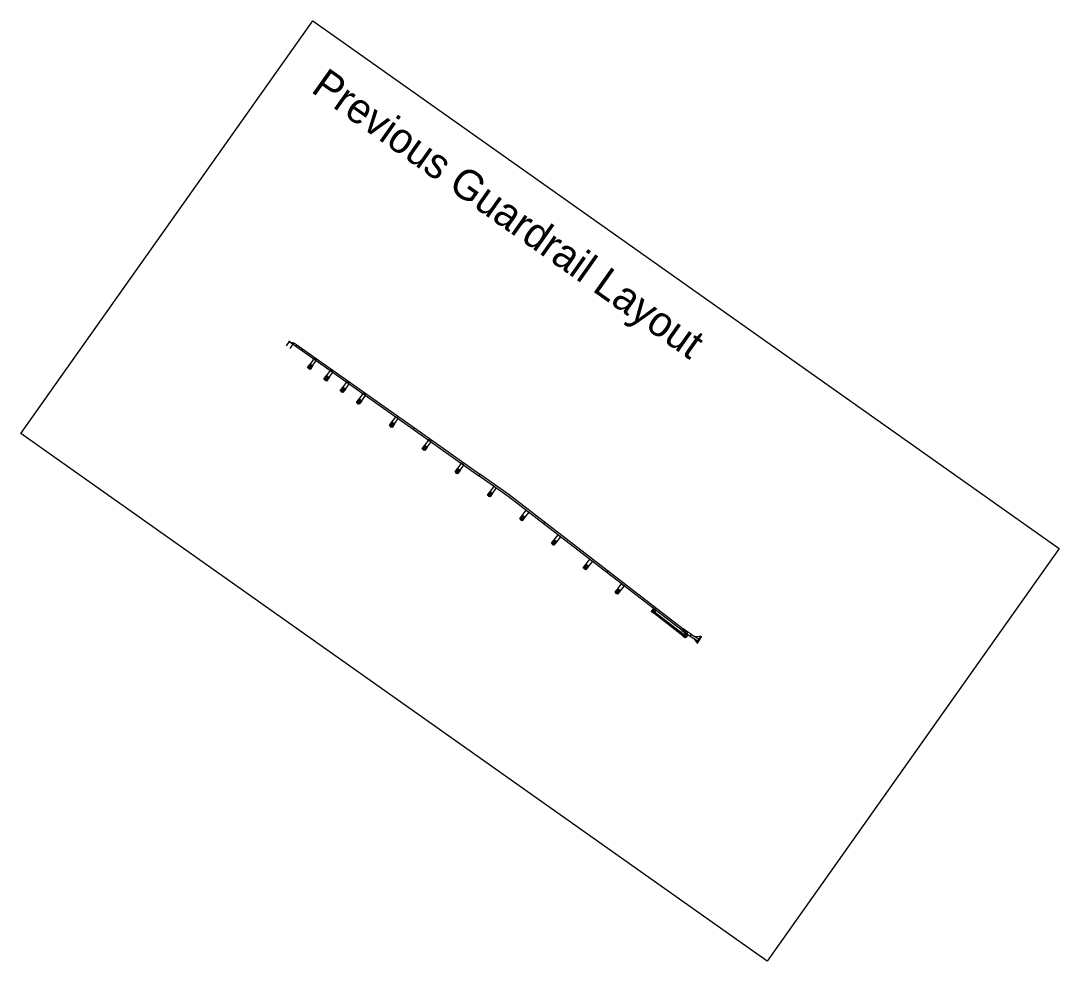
# Model space of a CAD drawing. Extents: x 16457860 to 16462445, y 6896068 to 6900243.
# Drawn here: x 16460800.2 to 16460961.9, y 6896067.7 to 6896214.1 of the extents above; entities that cross this region are included whole.
import ezdxf

# ---------------------------------------------------------------- set-up
doc = ezdxf.new("R2010")
doc.units = 0
doc.layers.add('Barrier', color=7, linetype='Continuous')
doc.layers.add('Draft_DNC', color=7, linetype='Continuous')

msp = doc.modelspace()

# ---------------------------------------------------------------- linework, layer by layer
at = {"layer": 'Barrier'}
for p, q in [((16460841.63, 6896163.5), (16460842.1, 6896164.17)), ((16460841.95, 6896164.24), (16460841.96, 6896164.26)), ((16460841.95, 6896164.24), (16460861.35, 6896150.51)), ((16460842.17, 6896164.12), (16460841.96, 6896164.26)), ((16460842.17, 6896163.11), (16460842.75, 6896163.93)), ((16460842.65, 6896163.96), (16460842.5, 6896164)), ((16460843.16, 6896163.72), (16460843, 6896163.5)), ((16460843.08, 6896163.77), (16460861.51, 6896150.73)), ((16460843.65, 6896163.37), (16460843.5, 6896163.15)), ((16460843.65, 6896163.37), (16460843.5, 6896163.15)), ((16460844.15, 6896163.02), (16460843.99, 6896162.8)), ((16460845.84, 6896161.49), (16460845.27, 6896160.67)), ((16460845.67, 6896160.38), (16460846.25, 6896161.2)), ((16460846.25, 6896161.2), (16460845.84, 6896161.49)), ((16460845.67, 6896160.38), (16460844.88, 6896160.13)), ((16460845.29, 6896159.84), (16460844.88, 6896160.13)), ((16460845.02, 6896160.03), (16460845.01, 6896160.01)), ((16460845.14, 6896159.92), (16460845.01, 6896160.01)), ((16460845.04, 6896159.99), (16460845.02, 6896159.96)), ((16460845.09, 6896159.92), (16460845.02, 6896159.96)), ((16460845.06, 6896159.98), (16460845.03, 6896159.95)), ((16460845.05, 6896159.94), (16460845.03, 6896159.92)), ((16460845.05, 6896159.91), (16460845.03, 6896159.92)), ((16460845.06, 6896159.93), (16460845.05, 6896159.91)), ((16460845.1, 6896159.95), (16460845.07, 6896159.92)), ((16460845.47, 6896160.53), (16460845.09, 6896159.98)), ((16460845.11, 6896159.95), (16460845.09, 6896159.92)), ((16460845.15, 6896159.94), (16460845.14, 6896159.92)), ((16460845.27, 6896160.67), (16460845.67, 6896160.38)), ((16460845.27, 6896160.67), (16460845.29, 6896159.84)), ((16460848.39, 6896159.68), (16460847.82, 6896158.87)), ((16460848.8, 6896159.39), (16460848.39, 6896159.68)), ((16460848.23, 6896158.58), (16460847.43, 6896158.32)), ((16460847.84, 6896158.03), (16460847.43, 6896158.32)), ((16460847.57, 6896158.22), (16460847.56, 6896158.21)), ((16460847.69, 6896158.12), (16460847.56, 6896158.21)), ((16460847.59, 6896158.19), (16460847.57, 6896158.16)), ((16460847.64, 6896158.11), (16460847.57, 6896158.16)), ((16460847.6, 6896158.14), (16460847.58, 6896158.12)), ((16460847.6, 6896158.1), (16460847.58, 6896158.12)), ((16460847.61, 6896158.18), (16460847.59, 6896158.15)), ((16460847.61, 6896158.13), (16460847.6, 6896158.1)), ((16460847.65, 6896158.15), (16460847.62, 6896158.12)), ((16460848.02, 6896158.72), (16460847.64, 6896158.18)), ((16460847.66, 6896158.14), (16460847.64, 6896158.11)), ((16460847.7, 6896158.13), (16460847.69, 6896158.12)), ((16460847.82, 6896158.87), (16460848.23, 6896158.58)), ((16460847.82, 6896158.87), (16460847.84, 6896158.03)), ((16460848.23, 6896158.58), (16460848.8, 6896159.39)), ((16460850.78, 6896156.77), (16460849.98, 6896156.52)), ((16460850.39, 6896156.23), (16460849.98, 6896156.52)), ((16460850.12, 6896156.42), (16460850.11, 6896156.41)), ((16460850.24, 6896156.31), (16460850.11, 6896156.41)), ((16460850.15, 6896156.38), (16460850.12, 6896156.35)), ((16460850.19, 6896156.31), (16460850.12, 6896156.35)), ((16460850.15, 6896156.33), (16460850.13, 6896156.31)), ((16460850.15, 6896156.3), (16460850.13, 6896156.31)), ((16460850.16, 6896156.37), (16460850.14, 6896156.34)), ((16460850.16, 6896156.32), (16460850.15, 6896156.3)), ((16460850.2, 6896156.35), (16460850.18, 6896156.31)), ((16460850.57, 6896156.92), (16460850.19, 6896156.37)), ((16460850.21, 6896156.34), (16460850.19, 6896156.31)), ((16460850.25, 6896156.33), (16460850.24, 6896156.31)), ((16460850.95, 6896157.88), (16460850.37, 6896157.06)), ((16460850.37, 6896157.06), (16460850.78, 6896156.77)), ((16460850.37, 6896157.06), (16460850.39, 6896156.23)), ((16460850.78, 6896156.77), (16460851.35, 6896157.59)), ((16460851.35, 6896157.59), (16460850.95, 6896157.88)), ((16460852.53, 6896154.71), (16460853.33, 6896154.97)), ((16460853.12, 6896155.11), (16460852.74, 6896154.57)), ((16460853.5, 6896156.07), (16460852.92, 6896155.26)), ((16460852.92, 6896155.26), (16460853.33, 6896154.97)), ((16460852.94, 6896154.42), (16460852.92, 6896155.26)), ((16460853.33, 6896154.97), (16460853.91, 6896155.78)), ((16460853.91, 6896155.78), (16460853.5, 6896156.07)), ((16460852.68, 6896154.49), (16460852.68, 6896154.48)), ((16460858.23, 6896151.5), (16460857.84, 6896150.96)), ((16460858.6, 6896152.46), (16460858.02, 6896151.65)), ((16460858.02, 6896151.65), (16460858.43, 6896151.36)), ((16460858.04, 6896150.81), (16460858.02, 6896151.65)), ((16460858.43, 6896151.36), (16460859.01, 6896152.17)), ((16460859.01, 6896152.17), (16460858.6, 6896152.46)), ((16460857.64, 6896151.1), (16460858.43, 6896151.36)), ((16460857.78, 6896150.88), (16460857.78, 6896150.87)), ((16460861.51, 6896150.73), (16460861.35, 6896150.51)), ((16460861.51, 6896150.73), (16460861.35, 6896150.51)), ((16460861.35, 6896150.51), (16460871.56, 6896143.29)), ((16460861.51, 6896150.73), (16460871.72, 6896143.51)), ((16460863.7, 6896148.85), (16460863.12, 6896148.04)), ((16460863.53, 6896147.75), (16460864.11, 6896148.56)), ((16460864.11, 6896148.56), (16460863.7, 6896148.85)), ((16460862.74, 6896147.49), (16460863.53, 6896147.75)), ((16460862.89, 6896147.27), (16460862.88, 6896147.26)), ((16460863.33, 6896147.89), (16460862.94, 6896147.35)), ((16460863.12, 6896148.04), (16460863.53, 6896147.75)), ((16460863.15, 6896147.2), (16460863.12, 6896148.04)), ((16460868.8, 6896145.24), (16460868.23, 6896144.43)), ((16460869.21, 6896144.95), (16460868.8, 6896145.24)), ((16460867.84, 6896143.88), (16460868.63, 6896144.14)), ((16460867.99, 6896143.66), (16460867.98, 6896143.65)), ((16460868.43, 6896144.28), (16460868.04, 6896143.74)), ((16460868.23, 6896144.43), (16460868.63, 6896144.14)), ((16460868.25, 6896143.59), (16460868.23, 6896144.43)), ((16460868.63, 6896144.14), (16460869.21, 6896144.95)), ((16460871.72, 6896143.51), (16460871.56, 6896143.29)), ((16460871.72, 6896143.51), (16460871.56, 6896143.29)), ((16460876.25, 6896140.3), (16460871.72, 6896143.51)), ((16460876.12, 6896140.07), (16460871.56, 6896143.29)), ((16460872.9, 6896140.28), (16460873.69, 6896140.53)), ((16460873.49, 6896140.68), (16460873.1, 6896140.13)), ((16460873.87, 6896141.66), (16460873.29, 6896140.82)), ((16460873.29, 6896140.82), (16460873.69, 6896140.53)), ((16460873.31, 6896139.99), (16460873.29, 6896140.82)), ((16460873.69, 6896140.53), (16460874.27, 6896141.35)), ((16460874.27, 6896141.35), (16460873.87, 6896141.66)), ((16460904.05, 6896118.89), (16460876.25, 6896140.3)), ((16460903.88, 6896118.67), (16460876.12, 6896140.07)), ((16460878.51, 6896136.96), (16460878.11, 6896136.43)), ((16460878.3, 6896136.28), (16460878.31, 6896137.11)), ((16460877.91, 6896136.58), (16460878.71, 6896136.81)), ((16460878.05, 6896136.35), (16460878.04, 6896136.35)), ((16460881.76, 6896136.06), (16460881.6, 6896135.85)), ((16460882.86, 6896132.77), (16460883.66, 6896132.99)), ((16460883, 6896132.54), (16460882.99, 6896132.53)), ((16460883.02, 6896132.64), (16460883.01, 6896132.64)), ((16460883.46, 6896133.15), (16460883.06, 6896132.62)), ((16460883.25, 6896132.46), (16460883.27, 6896133.3)), ((16460887.81, 6896128.95), (16460888.61, 6896129.18)), ((16460888.41, 6896129.33), (16460888.01, 6896128.8)), ((16460888.2, 6896128.65), (16460888.22, 6896129.48)), ((16460887.95, 6896128.72), (16460887.94, 6896128.72)), ((16460891.66, 6896128.43), (16460891.5, 6896128.22)), ((16460893.16, 6896124.83), (16460893.17, 6896125.67)), ((16460892.76, 6896125.14), (16460893.56, 6896125.36)), ((16460892.9, 6896124.91), (16460892.89, 6896124.9)), ((16460893.36, 6896125.52), (16460892.96, 6896124.99)), ((16460898.92, 6896122.5), (16460898.56, 6896122.02)), ((16460899.03, 6896122.41), (16460898.73, 6896122.64)), ((16460903.3, 6896118.38), (16460898.78, 6896121.86)), ((16460904.63, 6896118.57), (16460903.58, 6896119.27)), ((16460903.81, 6896119.12), (16460903.63, 6896118.85)), ((16460903.4, 6896119.01), (16460904.45, 6896118.31)), ((16460903.87, 6896118.67), (16460903.51, 6896118.2)), ((16460904.05, 6896118.89), (16460903.88, 6896118.67)), ((16460904, 6896118.58), (16460903.99, 6896118.57))]:
    msp.add_line(p, q, dxfattribs=at)
for points in [[(16460845.27, 6896160.67), (16460845.67, 6896160.38), (16460845.29, 6896159.84), (16460844.88, 6896160.13)], [(16460847.82, 6896158.87), (16460848.23, 6896158.58), (16460847.84, 6896158.03), (16460847.43, 6896158.32)], [(16460850.37, 6896157.06), (16460850.78, 6896156.77), (16460850.39, 6896156.23), (16460849.98, 6896156.52)], [(16460852.92, 6896155.26), (16460853.33, 6896154.97), (16460852.94, 6896154.42), (16460852.53, 6896154.71)], [(16460858.02, 6896151.65), (16460858.43, 6896151.36), (16460858.04, 6896150.81), (16460857.64, 6896151.1)], [(16460863.12, 6896148.04), (16460863.53, 6896147.75), (16460863.15, 6896147.2), (16460862.74, 6896147.49)], [(16460868.23, 6896144.43), (16460868.63, 6896144.14), (16460868.25, 6896143.59), (16460867.84, 6896143.88)], [(16460873.29, 6896140.82), (16460873.69, 6896140.53), (16460873.31, 6896139.99), (16460872.9, 6896140.28)], [(16460878.31, 6896137.11), (16460878.71, 6896136.81), (16460878.3, 6896136.28), (16460877.91, 6896136.58)], [(16460878.93, 6896137.91), (16460879.32, 6896137.6), (16460878.71, 6896136.81), (16460878.31, 6896137.11)], [(16460883.88, 6896134.09), (16460884.27, 6896133.79), (16460883.66, 6896132.99), (16460883.27, 6896133.3)], [(16460883.27, 6896133.3), (16460883.66, 6896132.99), (16460883.25, 6896132.46), (16460882.86, 6896132.77)], [(16460888.22, 6896129.48), (16460888.61, 6896129.18), (16460888.2, 6896128.65), (16460887.81, 6896128.95)], [(16460888.83, 6896130.28), (16460889.22, 6896129.97), (16460888.61, 6896129.18), (16460888.22, 6896129.48)], [(16460893.17, 6896125.67), (16460893.56, 6896125.36), (16460893.16, 6896124.83), (16460892.76, 6896125.14)], [(16460893.78, 6896126.46), (16460894.17, 6896126.16), (16460893.56, 6896125.36), (16460893.17, 6896125.67)], [(16460903.39, 6896119), (16460903.37, 6896118.97), (16460903.17, 6896119.11), (16460903.18, 6896119.14), (16460903.37, 6896119.42), (16460903.39, 6896119.45), (16460903.6, 6896119.31), (16460903.58, 6896119.28)]]:
    msp.add_lwpolyline(points, close=True, dxfattribs=at)
for points in [[(16460852.7, 6896154.54), (16460852.67, 6896154.5), (16460852.7, 6896154.48), (16460852.73, 6896154.52)], [(16460852.71, 6896154.59), (16460852.69, 6896154.55), (16460852.74, 6896154.51), (16460852.77, 6896154.55)], [(16460857.8, 6896150.93), (16460857.77, 6896150.89), (16460857.8, 6896150.87), (16460857.83, 6896150.91)], [(16460857.81, 6896150.98), (16460857.79, 6896150.94), (16460857.84, 6896150.9), (16460857.87, 6896150.94)], [(16460862.9, 6896147.32), (16460862.87, 6896147.28), (16460862.9, 6896147.26), (16460862.93, 6896147.3)], [(16460862.92, 6896147.37), (16460862.89, 6896147.33), (16460862.94, 6896147.29), (16460862.97, 6896147.33)], [(16460868, 6896143.71), (16460867.97, 6896143.67), (16460868, 6896143.65), (16460868.04, 6896143.69)], [(16460868.02, 6896143.76), (16460867.99, 6896143.72), (16460868.05, 6896143.68), (16460868.07, 6896143.72)], [(16460873.08, 6896140.15), (16460873.05, 6896140.12), (16460873.11, 6896140.08), (16460873.13, 6896140.11)], [(16460873.06, 6896140.11), (16460873.03, 6896140.07), (16460873.06, 6896140.04), (16460873.1, 6896140.09)], [(16460878.06, 6896136.41), (16460878.03, 6896136.37), (16460878.06, 6896136.34), (16460878.09, 6896136.39)], [(16460878.08, 6896136.45), (16460878.05, 6896136.42), (16460878.11, 6896136.38), (16460878.13, 6896136.41)], [(16460883.01, 6896132.59), (16460882.98, 6896132.55), (16460883.01, 6896132.53), (16460883.05, 6896132.57)], [(16460883.03, 6896132.64), (16460883, 6896132.6), (16460883.06, 6896132.56), (16460883.08, 6896132.6)], [(16460887.98, 6896128.82), (16460887.95, 6896128.79), (16460888.01, 6896128.75), (16460888.03, 6896128.78)], [(16460887.97, 6896128.78), (16460887.93, 6896128.74), (16460887.96, 6896128.71), (16460888, 6896128.76)], [(16460892.92, 6896124.96), (16460892.88, 6896124.92), (16460892.91, 6896124.9), (16460892.95, 6896124.94)], [(16460892.93, 6896125.01), (16460892.9, 6896124.97), (16460892.96, 6896124.93), (16460892.98, 6896124.97)], [(16460898.73, 6896122.65), (16460898.35, 6896122.16)], [(16460898.72, 6896122.63), (16460898.76, 6896121.87)], [(16460899.12, 6896122.33), (16460898.72, 6896122.63)], [(16460899.12, 6896122.34), (16460898.73, 6896122.65)], [(16460898.75, 6896121.86), (16460898.35, 6896122.16)], [(16460899.12, 6896122.33), (16460898.36, 6896122.17)], [(16460898.76, 6896121.87), (16460898.36, 6896122.17)], [(16460899.09, 6896122.29), (16460898.76, 6896121.87)], [(16460899.1, 6896122.28), (16460898.77, 6896121.86)], [(16460903.3, 6896118.37), (16460898.77, 6896121.86)], [(16460903.43, 6896118.54), (16460898.9, 6896122.02)], [(16460903.42, 6896118.53), (16460898.9, 6896122.02)], [(16460899.12, 6896122.33), (16460899.09, 6896122.29)], [(16460899.12, 6896122.31), (16460899.1, 6896122.28)], [(16460903.58, 6896119.28), (16460903.37, 6896119.42), (16460903.18, 6896119.14), (16460903.39, 6896119)], [(16460903.39, 6896119), (16460904.44, 6896118.3), (16460904.63, 6896118.58), (16460903.58, 6896119.28)], [(16460903.44, 6896118.55), (16460903.3, 6896118.37)], [(16460903.3, 6896118.34), (16460903.63, 6896118.09)], [(16460903.45, 6896118.54), (16460903.31, 6896118.36)], [(16460904.07, 6896118.51), (16460903.31, 6896118.36)], [(16460903.31, 6896118.36), (16460903.64, 6896118.11)], [(16460903.71, 6896118.05), (16460903.31, 6896118.36)], [(16460903.61, 6896118.78), (16460903.44, 6896118.55)], [(16460903.62, 6896118.77), (16460903.45, 6896118.54)], [(16460903.62, 6896118.8), (16460903.61, 6896118.78)], [(16460903.65, 6896118.83), (16460903.62, 6896118.8)], [(16460903.64, 6896118.79), (16460903.62, 6896118.77)], [(16460903.63, 6896118.09), (16460903.64, 6896118.11)], [(16460903.66, 6896118.82), (16460903.64, 6896118.79)], [(16460903.67, 6896118.82), (16460903.71, 6896118.05)], [(16460903.67, 6896118.82), (16460903.99, 6896118.57)], [(16460904.07, 6896118.51), (16460903.67, 6896118.82)], [(16460903.68, 6896118.83), (16460904, 6896118.58)], [(16460904.07, 6896118.51), (16460903.71, 6896118.05)], [(16460904.44, 6896118.3), (16460905.65, 6896117.58)], [(16460904.63, 6896118.58), (16460905.82, 6896117.88)], [(16460904.99, 6896117.97), (16460905.47, 6896117.29)], [(16460905.18, 6896118.26), (16460906.07, 6896118.29)], [(16460906.07, 6896118.29), (16460905.47, 6896117.29)], [(16460906.2, 6896118.2), (16460906.07, 6896118.28), (16460905.48, 6896117.29), (16460905.62, 6896117.21)], [(16460905.61, 6896117.2), (16460906.21, 6896118.21)], [(16460906.07, 6896118.29), (16460906.21, 6896118.21)], [(16460905.47, 6896117.29), (16460905.61, 6896117.2)]]:
    msp.add_lwpolyline(points, dxfattribs=at)
for centre, radius, start, end in [((16460898.76, 6896121.87), 0.0208, 232.3781, 322.3781), ((16460899.11, 6896122.33), 0.0208, 322.3781, 52.3781), ((16460903.31, 6896118.36), 0.0208, 142.3781, 232.3781), ((16460903.31, 6896118.36), 0.00517, 142.3781, 232.3781), ((16460903.66, 6896118.81), 0.0208, 52.3781, 142.3781), ((16460903.66, 6896118.81), 0.00517, 52.3781, 142.3781)]:
    msp.add_arc(centre, radius, start, end, dxfattribs=at)
for centre, major_axis, start_param, end_param in [((16460842.76, 6896165.32), (1.13, -0.8), 4.866664, 5.124351), ((16460842.28, 6896162.51), (-1.26, 0.89), 4.763936, 5.071137)]:
    msp.add_ellipse(centre, major_axis=major_axis, ratio=0.97085, start_param=start_param, end_param=end_param, dxfattribs=at)
at = {"layer": 'Draft_DNC'}
msp.add_lwpolyline([(16460845.71, 6896214.13), (16460961.9, 6896131.93), (16460916.44, 6896067.67), (16460800.25, 6896149.88)], close=True, dxfattribs=at)

# ---------------------------------------------------------------- texts
msp.add_text('Previous Guardrail Layout', height=4.6875, rotation=324.7216, dxfattribs=at).set_placement((16460845.25, 6896203.15))

doc.saveas('drawing.dxf')
